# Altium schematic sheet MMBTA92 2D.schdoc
size 127 x 101 mm
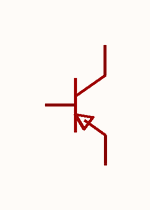
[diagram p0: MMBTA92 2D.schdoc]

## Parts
Q?  mmbta92(range:100-200)  [SOT-23-3_L2.9-W1.3-P1.90-LS2.4-BR]  (value not drawn)

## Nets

Not connected (* = marked no-connect by the designer): Q? 1(B) 2(E) 3(C)

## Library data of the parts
Q? = mmbta92(range:100-200): 晶体管类型:PNP;集电极电流(Ic):200mA;集射极击穿电压(Vceo):300V;耗散功率(Pd):300mW;直流电流增益(hFE):60;; Manufacturer: CJ(江苏长电/长晶); Symbol: MMBTA92 2D; AddInBom: yes; ModelId: c62791f0466c4ae2a892c056b845b0ca; ModelName: SOT-23-3P_L2.9-W1.3-H1.0-LS2.4-P0.95; ModelTransform: 98.425,114.173,0,180,0,0,0.0005,-0.0005,0; type: PNP; Current - Collector(Ic): 200mA; Collector - Emitter Voltage VCEO: 300V; Pd - Power Dissipation: 300mW; DC Current Gain: 60; Transition frequency(fT): 50MHz; Current - Collector Cutoff: 250nA; Vce Saturation(VCE(sat)): 200mV; Emitter-Base Voltage(Vebo): 5V; Number: 1个PNP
